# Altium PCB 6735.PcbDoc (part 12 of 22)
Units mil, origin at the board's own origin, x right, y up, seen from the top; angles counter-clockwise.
Board outline 2641.73 x 5165.35 mil, 6 copper layers (Top, Inner Layer 2, Inner Layer 3, Inner Layer 4, Inner Layer 5, Bottom), stack 35.7 mil thick; 1011 components, 790 nets, 4118 pads, 9325 vias.
Unrouted connection lines stored in the file: 4610.
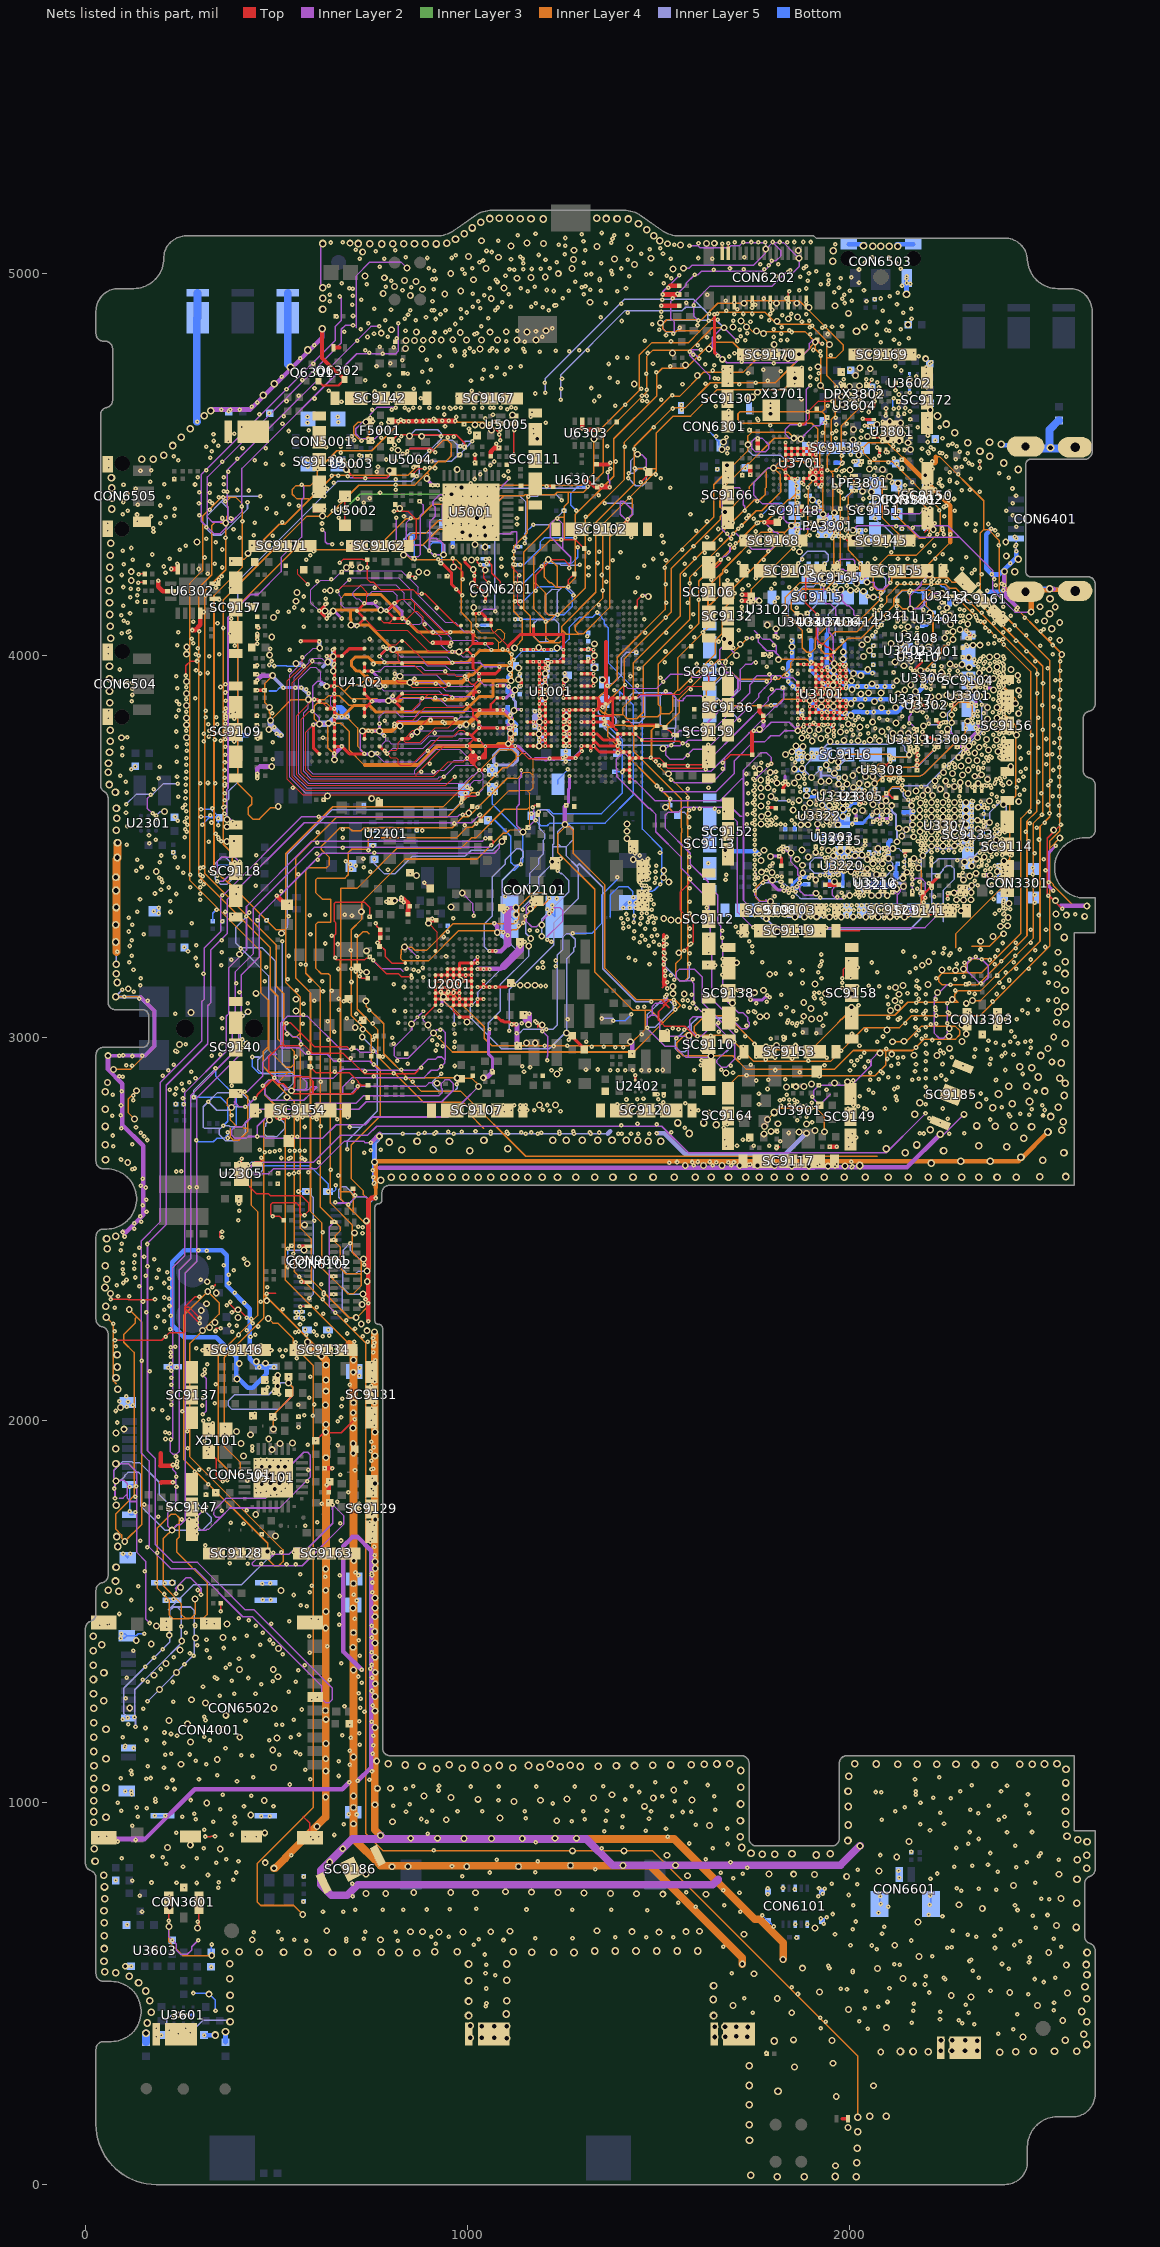
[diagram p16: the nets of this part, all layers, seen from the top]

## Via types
v1: diameter 12, hole 4, Top to Inner Layer 2, 3329 vias
v2: diameter 12, hole 4, Inner Layer 5 to Bottom, 3071 vias
v3: diameter 18, hole 10, Inner Layer 2 to Inner Layer 5, 1928 vias
v4: diameter 10, hole 4, Top to Inner Layer 2, 525 vias
v5: diameter 20, hole 12, Top to Bottom, 472 vias

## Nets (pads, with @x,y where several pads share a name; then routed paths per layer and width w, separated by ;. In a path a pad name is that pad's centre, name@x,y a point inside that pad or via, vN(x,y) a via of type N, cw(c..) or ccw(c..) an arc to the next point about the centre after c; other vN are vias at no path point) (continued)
D_GND: (continued)
  other v2: 198.3,391.09 2047.13,407.53 1923.89,409.43 2285.09,430.29 2235.79,432.18 1922.94,435.97 2165.63,454.93 2038.6,461.57 2303.58,470.19 1049.27,474.48 2098.32,477.69 1864.16,498.54 2466.16,497.6 2207.35,502.34 2042.39,506.13 1048.41,513.45 1976.03,512.76 2506.93,529.83 2250.01,537.41 2337.23,541.21 2198.82,545 1046.68,552.43 2007.31,559.22 2415.44,564.91 1946.64,565.85 119.31,571.09 2130.56,575.33 2468.53,581.97 2313.05,584.82 1044.94,601.79 2069.88,615.15 182.31,618.96 2379.59,618.88 2255.22,619.89 2553.38,621.79 2001.62,626.53 1015.5,626.91 916.76,630.38 682.05,636.44 577.25,637.3 817.16,637.3 2445.78,636.96 227.31,639.09 514.03,641.63 727.95,643.37 2330.12,648.33 2084.1,655.92 440.61,660.01 2269.44,663.5 2394.59,668.24 2015.84,688.15 2478.96,703.32 2206.44,706.05 2074.86,711.2 674.24,713.4 621.41,714.13 1712.74,714.02 1469.55,717.16 705.92,718.49 778.29,718.49 831.51,718.49 893.23,719.55 1153.91,719.51 1273.74,718.72 1375.56,718.72 952.83,720.61 1022.01,721.68 1597.12,726.44 1671.17,731.24 2009.07,730.65 2432.03,730.81 1551.19,737.41 2521.15,746.93 698.97,754.1 1997.06,757.53 1711.17,763.37 1571.76,764.84 1669.11,770.32 2337.23,774.42 2279.84,774.73 2019.37,786.14 238.3,789.58 291.41,789.01 172.77,790.14 349.03,790.71 386.89,796.92 1695.17,801.18 985.56,806.74 2228.41,813.69 1662.26,815.57 1057.75,816.3 1176.64,817.36 2387.38,818.37 2021.09,823.32 1334.27,824.79 1731.53,828.37 959.03,833.28 2320.16,834.15 1687.63,843 2462.37,843.63 1183.01,846.02 2546.75,849.32 1075.79,850.27 1622.49,850.54 368.81,851.16 291.11,853.5 202.12,856 538.3,861.33 2079.31,862.09 2499.34,866.38 2367.57,867.33 911.26,874.68 309.49,879.4 1351.26,879.99 1641,880.02 2278.45,880.6 1680.08,890.99 1579.3,892.36 1177.7,895.91 84.63,897.42 131.51,901.55 595.36,902.57 1523.76,910.19 382.39,914.66 895.33,918.2 2411.18,921.37 2313.53,922.32 2476.59,922.32 1357.63,924.57 1466.17,925.27 310.75,927.87 1518.98,930.94 1678.71,931.44 1404.33,935.19 122.73,939.15 1597.12,941.04 2183.65,942.23 2246.22,944.12 334.47,948.95 1272.31,950.09 2083.16,954.55 1306.14,955.36 878.35,956.42 1474.4,957.5 1152.22,958.54 389.9,962.1 2404.54,962.13 284.84,970.48 2236.74,972.56 2336.28,971.61 1562.84,974.64 2118.23,976.35 93.25,978.1 1364.53,977.65 1647.86,980.12 133.76,986.49 2362.83,991.52 2461.42,992.47 848.63,994.63 183.31,1000.98 1541.59,1002.75 275.23,1006 2264.23,1010.48 2217.78,1012.38 1645.12,1015.78 434.14,1017.61 358.9,1019.88 2172.27,1019.96 2082.21,1026.6 233.03,1034.83 1007.86,1041.34 1081.1,1041.34 1179.82,1041.34 1280.67,1041.34 857.12,1042.4 1354.97,1042.4 1429.28,1042.4 925.06,1043.46 2411.18,1043.67 1627.98,1045.26 2319.22,1044.61 534.59,1046.66 1490.85,1052.11 1571.07,1052.11 396.48,1055.59 227.64,1058.32 296.96,1060.31 588.4,1060.44 2170.37,1060.73 158.91,1061.93 91.85,1063.32 2233.89,1065.47 438.6,1065.75 662.82,1068.95 344.92,1070.42 119.1,1082.88 574.58,1084.89 205.44,1090.15 316.17,1099.18 662.82,1107.22 436.09,1122.15 208.27,1124.6 273.34,1125.21 561.82,1125.29 126.47,1142.05 102.5,1144.17 206.45,1155.17 97.33,1169.79 310.94,1172.07 239.48,1174.52 672.38,1175.26 558.63,1176.32 206.76,1182.71 515.05,1202.9 310.94,1224.16 730,1237.42 565.84,1242.91 441.69,1246.48 677.7,1251.8 351.33,1278.38 389.6,1283.69 444.88,1283.69 532.06,1289.01 307.5,1301.91 162.49,1315.35 550.13,1315.58 639.43,1320.9 344.06,1323.19 196.64,1348.85 745,1349.95 155.95,1354.46 573.52,1359.17 259.03,1361.16 377.67,1361.6 669.58,1363.76 179.43,1378.29 230.75,1379.33 283.55,1383.77 587.34,1391.06 316.98,1397.65 201.81,1400.67 632.13,1408.1 457.69,1412.82 316.68,1425.27 585.82,1434.71 422.24,1435.7 250.58,1460.05 287.64,1460.33 748.75,1462.47 62.58,1466.24 486.5,1467.24 533.59,1474.13 316.98,1475.27 401.55,1482.01 88.2,1492.85 563.33,1515.25 119.73,1529.31 138.45,1565.77 185.31,1574.09 749.69,1593.75 561.73,1596.88 187.75,1652.98 161.19,1667.83 313.26,1672.74 143.42,1684.71 668.59,1685 750.62,1690.33 286.78,1716.26 574.62,1723.43 413.6,1728.84 666.62,1730.33 380.45,1731.54 606.51,1732.3 271.26,1740 190.6,1747 751.56,1757.84 356.77,1763.34 421.53,1763.94 315.78,1771.82 153.47,1779.26 617.92,1780.93 658.74,1786.49 130.65,1799.96 687.48,1811.08 752.5,1815.04 631.45,1830.32 321.59,1831.67 358.8,1839.79 580.37,1840.47 423.75,1841.82 666.63,1856.94 285.64,1865.28 582.4,1869.56 705.19,1868.88 322.12,1871.53 753.44,1872.24 238.73,1886.13 316.91,1919.48 267.92,1926.78 754.38,1929.44 660.37,1934.08 581.72,1935.86 310.65,1944.5 208.5,1968.48 265.83,1970.56 557.37,1981.19 755.31,1986.64 332.54,1991.41 660.37,1996.62 594.92,2010.96 253.32,2022.68 201.2,2025.81 177.23,2028.93 556.69,2040.73 337.76,2044.57 756.25,2043.84 671.84,2056.04 585.44,2058.32 340.88,2093.56 757.19,2101.04 588.15,2113.12 311.7,2122.75 167.85,2127.96 238.31,2138.09 147,2155.06 758.13,2156.36 553.01,2162.36 515.48,2167.57 594.7,2174.87 486.67,2182.8 318.47,2187.38 290.33,2188.42 235.08,2191.55 666.63,2191.55 623.33,2192.28 458.25,2196.33 756.16,2202.39 549.59,2203.78 703.62,2204.79 210.06,2218.65 431.8,2218.66 605.06,2222.04 401.27,2223.98 685.18,2226.69 548.91,2230.16 184.25,2241.66 451.49,2245.05 206.48,2258.7 433.61,2264.67 189.22,2271.81 586.73,2277.37 621.99,2277.93 158.54,2282.26 206.54,2289.3 515.74,2290.09 76.19,2294.2 605.07,2295.28 369.17,2300.5 415.25,2307.45 150.55,2310.28 458.54,2310.03 181.92,2316.63 205.9,2320.82 85.23,2323.68 114.69,2323.93 623.12,2328.71 390.76,2332.92 172.32,2345.11 140.75,2349.99 81.88,2352.82 375.6,2358.18 206.58,2358.71 107.39,2366.67 130.45,2373.25 186.09,2372.92 158.17,2378.26 214.18,2386.98 191.5,2392.91 97.63,2395.02 127.19,2395.85 162.34,2402.36 361.98,2404.83 127.49,2412.39 180.34,2420.99 322.92,2424.45 153.25,2427.13 129.44,2431.86 295.68,2444.35 316.9,2443.67 141.1,2451.35 161.17,2460.75 102.18,2480.42 621.25,2491.06 128.17,2500.19 713.69,2505.94 145.68,2518.83 598.49,2521.32 159.8,2545.38 158.67,2576.45 158.11,2608.65 272.46,2609.17 291.24,2609.59 149.63,2631.24 661.55,2639.98 237.45,2650.37 250.68,2651.61 641.71,2655.01 122.52,2656.66 2006.96,2664.22 1915.23,2665.35 1961.09,2664.78 1591.04,2666.48 1823.49,2666.48 1869.36,2665.91 1641.72,2667.33 1689.57,2666.76 1782.72,2667.05 1736,2667.61 610.44,2674.86 574.36,2680.87 92.58,2682.65 532.26,2683.88 72.66,2716.51 1704.67,2717.7 1748.92,2717.7 1788.59,2718.21 1817.58,2729.4 162.19,2732.81 153.25,2742.3 71.06,2744.56 1445.76,2749.5 2259.51,2749.06 1403.59,2749.69 2182.5,2750.2 2299.15,2750.2 1840.47,2751.27 144.27,2751.64 887.39,2752.22 1192.87,2751.87 1344.43,2752.51 917.1,2752.92 1139.74,2753.27 1166.65,2752.92 1532.99,2753.49 2044.05,2753.31 949.26,2753.97 1101.99,2753.97 1239.35,2753.97 1319.74,2753.62 2078.03,2754.16 984.91,2755.01 1060.4,2755.01 1275.7,2755.36 1020.56,2756.06 1567.56,2765 132.24,2765.93 573.61,2766.99 615.99,2769.08 1402.28,2771.14 1679.65,2774.09 1444.35,2775.08 1495.19,2774.64 1862.34,2784.33 2367.1,2786.44 605.52,2786.87 658.37,2786.87 553.72,2787.92 1710.78,2787.89 2256.03,2788.38 2207.16,2789.73 686.1,2792.63 1735.7,2795.51 70.26,2795.87 2469.03,2798.9 2415.8,2800.03 1631.95,2807.25 1666.02,2807.25 2509.8,2811.35 2243.47,2815.29 2037.68,2816.18 418.21,2820.06 1878.43,2820.49 2021.41,2821.43 1121.65,2823.38 1151.83,2823.49 1093.49,2823.94 1137.31,2823.78 1208.73,2824.42 1502.36,2823.91 1762.15,2826.03 1391.36,2826.6 1568.98,2828.86 1862.43,2832.72 125.12,2837.11 1817.08,2836.92 2122.87,2836.81 255.13,2842.09 1901.53,2846.55 2026.12,2847.77 124.82,2849.29 2275.65,2849.5 71.66,2851.19 2212.54,2851.61 234.31,2853.09 1762.15,2853.49 2317.73,2854.41 2060.99,2856.53 399.18,2859.11 2241.23,2859.67 256.2,2863.62 1938.94,2864.18 220.46,2864.9 1784.48,2866.32 2116.45,2866.34 237.28,2867.55 382.28,2874.99 252.28,2879.64 271.5,2883.55 615.28,2884.84 699.64,2884.84 855.78,2885.15 1755.02,2888.59 2009.28,2888.57 2251.56,2890.32 2382.96,2890.18 1786.62,2890.91 1830.44,2891.44 2180.29,2893.01 838.51,2894.45 2224.69,2893.96 287.94,2894.79 2126.44,2896.79 88.09,2900.09 754.34,2900.13 1919.53,2899.91 1729.6,2901.81 806.68,2907.31 2085.81,2908.13 2053.4,2909.02 276.49,2910.97 1147.35,2911.02 1868.93,2910.68 2268.15,2910.96 652.4,2911.84 731.35,2912.51 1219.32,2915.23 1372.76,2915.4 1392.55,2915.29 1412.34,2915.18 1432.13,2915.08 1453.85,2914.97 1474.72,2915.08 1495.58,2915.18 1593.04,2915.07 826.51,2916.56 1309.52,2916.16 1510.31,2916.04 1804.27,2915.97 1340.15,2917.26 1242.99,2917.9 1163.12,2922.96 931.33,2925.17 1142.89,2925.99 965.85,2926.61 1688.65,2926.73 106.53,2928.55 1933.7,2928.25 1609.82,2928.8 753.95,2930.49 1740.97,2930.14 2366.13,2931.56 843.16,2932.08 2243.51,2931.65 2003.62,2938.64 2047.7,2939.03 815.34,2940.18 1611.86,2941.52 1891.37,2940.61 663.6,2941.75 1779.69,2943.52 1848.67,2945.25 2097.52,2944.88 694.24,2946.93 1710.52,2948.09 1804.1,2948.09 1939.37,2948.09 2139.95,2949.09 2028,2950.3 2266.19,2949.79 1550.9,2950.95 1754.77,2951.14 2325.78,2950.64 2397.34,2952.6 330.16,2953.79 352.91,2956.65 1908.15,2959.59 2200.96,2958.91 2465.71,2959.61 235.59,2965.85 753.45,2965.62 1878.91,2966.04 916.31,2967.15 1977.15,2966.59 2236.53,2967.08 1613.89,2968.47 965.31,2975.09 1407.29,2975.46 1386.44,2975.67 1324.8,2976.7 1355.77,2977.11 1721.13,2977.38 935.31,2978.09 1224.95,2978.77 1260.27,2978.97 2025.17,2979.47 1201.62,2979.8 1857.73,2981.35 2402.95,2980.65 920.31,2982.09 1750.42,2983.99 806.31,2985.09 356.47,2986.5 2439.77,2986.26 1619.99,2987.29 1309.72,2989.5 966.31,2990.09 2362.63,2992.21 2472.73,2991.87 907.01,2994.23 2215.6,2994.46 635.12,2994.7 753.15,2995.23 1792.54,2997.36 2187.64,2997.48 1546.03,2999.14 802.94,3000.09 926.31,3002.09 1825.26,3003.1 2086.65,3003.8 1725.89,3004.66 1636.27,3006.11 1854.91,3008.63 1455.41,3009.95 2005.5,3010.44 966.31,3011.09 1912.15,3012.59 1877.02,3015.17 650.48,3016.43 1657.12,3015.77 2421.88,3017.82 1702.44,3019.1 2043.05,3020.02 2180.39,3020.02 928.31,3021.09 357.57,3025.39 1859.9,3031.36 1729.63,3032.17 1929.65,3032.09 2211.3,3035.79 568.31,3037.09 751.35,3037.69 1141.94,3038.11 2144.86,3038.16 1752.06,3038.95 818.31,3040.09 2347.51,3042.29 634.17,3043.38 1176.31,3044.09 1838.28,3046.35 2125.83,3048.24 1703.79,3049.32 2406.45,3048.68 357.29,3051.68 683.54,3051.66 2100.12,3053.21 2003.15,3057.09 569.31,3061.09 1819.38,3061.46 709.01,3062.5 1936.65,3063.09 2192.57,3063.07 235.26,3063.64 2259.65,3064.02 2465.71,3064.81 1752.51,3067.37 2313.5,3066.85 836.89,3070.06 1852.04,3070.03 807.41,3071.15 926.31,3071.09 2162.34,3070.63 742.92,3072.21 2224.72,3072.29 2491.66,3073.23 662.89,3073.8 1834.19,3080.02 1445.22,3080.65 1461.75,3081.43 2022.65,3085.59 570.56,3089.44 1755.22,3090.38 1932.28,3090.38 424.28,3091.11 1540.07,3092.37 1782.74,3094.44 2374.19,3094.27 598.07,3096.82 2467.01,3099.33 2518.89,3098.94 2180.29,3101.81 662.33,3102.91 1905.06,3107.5 1784.09,3111.13 1820.72,3113.2 2150.76,3117.16 403.08,3119.48 963.31,3119.09 929.09,3120.91 948.95,3120.83 621.4,3121.86 644.15,3123.44 552.4,3124.62 1521.64,3129.22 2181.23,3129.21 833.31,3133.09 2018.59,3134.68 2076.91,3134.79 2049.91,3136.76 806.31,3140.09 394.43,3142.64 2312.82,3143.36 2342.98,3142.66 1876.07,3143.66 2391.37,3144.76 2519.68,3144.88 695.95,3146.35 1522.69,3145.86 619.3,3148.29 469.16,3148.62 586.67,3149.28 2175.56,3149.99 2417.32,3152.48 528.8,3153.63 1925.65,3155.59 853.31,3157.09 2002.15,3157.59 883.31,3159.09 1844.89,3167.28 308.85,3168.24 2071.27,3171.47 2509.78,3171.02 1917.64,3172 871.31,3174.09 1876.07,3176.72 859.31,3178.09 661.62,3180.35 695.95,3180.55 840.31,3181.09 2435.79,3180.73 2468.52,3181.23 2172.73,3182.11 882.31,3184.09 1183.21,3183.79 1197.07,3184.23 2020.62,3184.28 472.83,3184.65 292.75,3189.35 355.77,3189.82 1648.15,3189.75 576.17,3191.41 1923.31,3190.9 562.91,3193.15 1475.78,3192.77 2509.78,3194.38 114.76,3197.44 1770.3,3197.56 2057.47,3197.23 1195.71,3197.82 1842.51,3198.17 1229.95,3202.54 1997.65,3202.09 752.68,3203.49 1438.85,3202.76 2473.43,3205.08 288.33,3209.03 653.38,3210.21 1421.83,3210.06 2169.9,3212.35 532.26,3214.35 943.31,3214.09 2259.71,3215.99 1515.31,3221.09 1489.95,3221.83 1580.8,3221.91 2219.27,3222.85 356.32,3224.16 2139.94,3226.03 693.59,3228.89 2387.19,3229.35 2484.56,3229.7 2287.99,3231.24 2341.84,3231.24 2247.37,3234.08 2510.97,3237.82 115.54,3240.44 1473.31,3241.09 289.93,3241.96 1501.31,3244.09 1581.09,3243.88 1520.31,3245.09 659.95,3245.64 627.6,3247.08 2400.42,3248.25 2472.73,3248.56 764.06,3249 1450.31,3250.09 1486.31,3252.09 356.6,3255.14 1464.96,3257 1434.31,3261.09 937.51,3264.07 1521.31,3264.09 1481.31,3266.09 1580.56,3266.17 708.58,3266.78 1455.31,3267.09 644.59,3267.62 1496.31,3269.09 1718.06,3270.11 152.31,3271.09 588.73,3270.72 1731.93,3275.26 1707.94,3276.96 113.6,3278.4 1435.31,3279.09 1760.68,3279.07 1162.07,3281.46 1181.99,3280.91 2473.43,3282.93 2513.08,3283.23 1489.31,3284.09 1464.31,3286.09 1580.56,3286.16 1406.78,3287 1701.31,3290.56 1747.58,3290.06 1421.31,3291.09 1134.11,3292.9 1719.9,3292.88 1451.31,3298.09 277.89,3300.19 1407.31,3300.09 1145.42,3301.49 1487.31,3301.09 1625.31,3301.09 1471.31,3303.09 1419.31,3310.09 1402.31,3313.09 2089.65,3313.59 113.21,3314.03 1455.95,3314.49 1962.65,3314.59 2057.65,3314.59 2122.52,3315.04 1897.75,3316.27 1931.65,3316.59 1993.65,3316.59 2025.65,3316.59 1151.37,3317.97 1482.61,3317.97 697.31,3320.09 586.52,3320.69 2494.47,3321.5 627.84,3322.03 677.95,3321.84 2401.65,3323.59 1415.31,3324.09 2379.65,3324.59 1455.95,3326.49 1468.95,3326.49 1581.31,3326.09 2240.33,3327.26 222.47,3329.5 365.95,3329.49 2274.65,3329.59 1720.29,3333.06 2390.65,3333.59 2207.36,3333.92 1481.31,3335.09 2252.72,3335.3 2401.65,3339.59 2273.65,3342.59 2306.65,3343.59 1803.65,3346.59 2218.65,3348.59 1486.95,3349.83 532.95,3352.49 1470.31,3352.09 2483.58,3353.7 832.26,3355.13 2401.65,3354.59 1581.31,3356.09 222.19,3357.06 787.33,3356.63 1480.77,3361.91 2376.65,3362.59 1233.24,3364.7 826.31,3367.29 1467.39,3367.09 1922.06,3367.3 1433.31,3368.09 1966.65,3368.59 1984.65,3368.59 2024.65,3368.59 2220.65,3369.59 1803.16,3370.61 2519.13,3371.86 357.43,3372.81 2036.65,3372.59 2014.65,3375.59 2291.65,3375.59 2483.22,3375.05 393.95,3376.49 237.95,3376.6 181.85,3377.87 1978.65,3379.59 2411.94,3378.77 2369.65,3380.59 2162.65,3384.59 197.61,3387.32 2017.65,3387.59 2037.65,3387.59 1581.17,3391.03 2176.65,3390.59 2301.65,3391.59 2419.33,3393.34 217.78,3393.63 273.89,3394.26 400.3,3394.52 1861.65,3395.59 2285.65,3394.59 2480.43,3397.32 445.96,3398.42 1466.95,3398.49 2022.65,3398.59 309.95,3401.49 2163.65,3401.59 2370.8,3402.42 2402.65,3404.59 1868.21,3406.21 2520.75,3407.23 2182.25,3408.33 2326.65,3411.59 2479.4,3411.21 1455.62,3412.82 1467.95,3413.49 198.24,3415.06 2162.65,3414.59 1581.24,3416.57 1869.61,3418.2 1892.35,3418.33 162.3,3418.84 400.02,3419.34 1760.65,3418.59 2401.65,3418.59 1822.2,3421.44 1946.65,3420.59 306.95,3423.49 1810.28,3423.17 1922.65,3425.59 1935.65,3425.59 1968.62,3425.42 274.52,3427.04 1956.66,3427.22 2163.65,3427.59 2478.88,3428.24 256.19,3431.75 2295.65,3432.59 745.59,3434.81 133.3,3437.12 1949.76,3437.06 2402.65,3436.59 1936.79,3438.02 1962.67,3437.99 1782.71,3439.17 2511.9,3438.7 791.57,3440.1 695.71,3441.4 2163.65,3440.59 2368.65,3443.59 2296.65,3445.59 241.74,3445.95 307.95,3446.49 1580.14,3446.03 2478.88,3445.61 146.54,3447.21 728.44,3446.72 2337.65,3447.59 2398.49,3448.23 1790.47,3448.61 447.14,3451.26 2413.72,3452.18 2165.65,3453.59 1798.7,3457.37 680.59,3462.48 2182.65,3462.59 2280.65,3464.59 2315.65,3465.59 135.66,3466.4 608.19,3466.08 727.39,3468.42 2507.77,3467.93 1934.65,3471.59 233.54,3472.43 1972.65,3473.59 1985.65,3473.59 1998.65,3473.59 257.5,3473.69 1579.63,3474.1 446.96,3478.18 2418.5,3479.11 1926.65,3481.59 2075.01,3480.61 2088.65,3480.59 605.77,3482.1 2483.75,3483.18 755.62,3484.33 1503.22,3484.14 2339.65,3484.59 740.49,3490.71 2009.65,3491.59 2022.65,3491.59 1959.65,3493.59 1819.06,3495.5 1926.65,3494.59 2352.65,3495.59 2422.56,3495 2096.65,3497.59 2192.65,3497.59 673.52,3497.86 1579.63,3497.7 2293.65,3499.59 2384.65,3498.59 2228.65,3503.59 2258.65,3503.59 107.79,3505.41 2188.65,3509.59 606.68,3510.83 2317.65,3511.59 322.73,3513.48 2177.71,3514.56 2467.94,3514.26 2198.65,3516.59 2228.65,3516.59 2258.65,3516.59 2288.65,3516.59 2401.65,3519.59 2494.89,3519.07 348.28,3519.9 1579.31,3522.09 672.93,3523.36 2187.65,3522.59 2324.65,3524.59 2198.65,3529.59 2228.65,3529.59 2258.65,3529.59 2288.65,3529.59 340.61,3534.25 2391.65,3534.59 607.29,3537.74 2405.31,3538.09 2460.58,3539.6 2165.65,3541.59 866.95,3542.83 881.58,3542.68 2198.65,3542.59 2228.65,3542.59 2258.65,3542.59 2288.65,3542.59 2318.65,3542.59 738.91,3544.09 260.65,3545.56 672.93,3545.46 2489.28,3549.94 1579.31,3551.09 108.96,3553.35 1930.65,3555.59 1947.65,3554.59 2198.65,3555.59 2228.65,3555.59 2258.65,3555.59 2288.65,3555.59 2318.65,3555.59 2350.65,3554.59 992.74,3556.64 1782.65,3557.59 1794.65,3557.59 1806.65,3557.59 1729.65,3558.59 1818.65,3559.59 2405.31,3559.09 965.36,3561.08 1022.85,3560.84 1744.65,3561.59 2470.41,3561.68 329.78,3563.52 2509.64,3562.76 1954.65,3565.59 260.02,3565.73 1847.65,3569.59 2198.65,3568.59 2228.65,3568.59 2258.65,3568.59 2288.65,3568.59 2318.65,3568.59 2348.65,3568.59 1782.65,3570.59 1794.65,3570.59 1923.65,3573.59 1964.68,3572.69 1806.65,3575.59 1910.65,3575.59 1952.65,3577.59 610.31,3579.09 1862.65,3578.59 2198.65,3581.59 2228.65,3581.59 2258.65,3581.59 2288.65,3581.59 2318.65,3581.59 1030.9,3582.54 2106.88,3582.51 326.57,3582.77 1932.65,3582.59 1996.65,3583.59 2058.85,3583.31 2502.58,3583.4 2085.03,3583.84 1731.65,3585.59 1966.65,3584.59 1745.65,3587.59 1944.65,3586.59 2350.65,3586.59 2522.25,3588.24 106.03,3589.6 2471.03,3591.34 1954.65,3593.59 1936.65,3595.59 2198.65,3594.59 2228.65,3594.59 2258.65,3594.59 2288.65,3594.59 2318.65,3594.59 1579.31,3595.98 1966.65,3597.59 1996.65,3596.59 332.19,3601.22 2360.65,3600.59 254.03,3602.29 360.26,3602.82 1025.3,3603.2 1784.88,3602.64 2376.94,3606.36 2198.65,3607.59 2228.65,3607.59 2258.65,3607.59 2288.65,3607.59 2318.65,3607.59 1911.65,3609.59 1993.65,3608.59 2351.65,3609.59 2518.34,3609.47 1966.65,3610.59 1731.65,3612.59 1850.65,3613.59 2040.65,3613.59 1745.65,3615.59 1786.65,3615.59 2003.65,3617.59 2386.94,3617.36 2493.17,3617.32 2322.68,3619.59 2198.65,3620.59 2228.65,3620.59 2258.65,3620.59 2288.65,3620.59 1914.65,3622.59 1940.65,3622.59 1953.65,3622.59 1966.65,3623.59 2152.65,3623.59 2165.65,3622.59 1927.65,3624.59 1994.65,3625.59 1575.31,3628.09 2176.65,3628.59 242.68,3630.66 2530.67,3632.04 2063.65,3637.59 1733.65,3639.59 2500.5,3639.76 107.79,3641.64 1870.34,3643.99 1746.65,3646.59 1801.65,3647.59 2455.81,3649.12 1575.31,3652.09 1630.11,3653.97 2320.78,3655.44 1868.65,3657.59 2186.65,3656.59 2221.65,3656.59 2258.65,3659.59 2353.06,3661.5 2366.65,3660.59 2518.65,3661.59 1838.72,3662.91 1074.31,3664.09 364.98,3664.7 1730.65,3665.59 1881.65,3664.59 2396.77,3665.05 1824.65,3665.7 300.05,3666.6 320.56,3666.99 339.13,3666.6 2380.65,3668.59 105.45,3669.7 1795.65,3673.59 2526.05,3672.96 2271.65,3674.59 1746.65,3677.59 1880.65,3677.59 2392.65,3679.59 1785.65,3680.59 1806.65,3681.59 2233.65,3682.59 2454.15,3683.59 90.96,3686.13 1728.65,3690.59 2493.17,3695.72 1806.65,3696.59 2052.88,3700.14 2532.28,3700.86 1622.6,3702.89 2459.99,3704.67 2348.7,3706.57 1748.65,3707.59 2258.65,3706.59 2275.06,3707 2335.65,3707.59 2046.65,3711.59 2059.65,3711.59 2322.65,3710.59 1576.31,3712.09 1784.65,3713.59 2514.17,3715.57 1627.42,3717.11 1767.65,3719.59 2269.65,3719.59 2350.65,3719.59 1856.65,3721.59 1875.65,3721.59 1256.31,3723.09 2408.07,3729.82 1847.65,3730.59 2393.65,3731.59 2356.65,3733.59 2370.65,3733.59 1860.65,3734.59 1873.65,3734.59 1905.65,3734.59 96.41,3739.1 1575.31,3739.09 1969.65,3738.59 2344.65,3740.59 2515.65,3740.59 2529.84,3742.5 2310.65,3743.59 1913.65,3744.59 2403.06,3745 2467.53,3746.56 1865.65,3746.59 1878.65,3746.59 1900.65,3746.59 2297.65,3747.59 1629.42,3748.25 1256.31,3750.09 782.79,3751.07 895.01,3751.7 2168.65,3752.59 1926.47,3756.66 96.11,3759.37 2493.17,3758.94 2158.65,3761.59 2376.65,3763.59 2396.61,3763.09 2409.06,3764 1575.31,3766.09 2353.56,3766 1629.02,3767.41 2188.55,3769.11 2324.65,3771.59 2534.89,3771.72 1966.65,3773.59 2037.65,3773.59 389.4,3775.52 2003.65,3775.59 2139.65,3774.59 2155.65,3775.59 309.09,3776.01 354.22,3777.99 338.87,3779.63 2120.65,3781.59 2514.04,3782.14 1644.15,3783.59 2401.65,3782.59 621.47,3785.41 322.72,3788.27 1889.65,3788.59 1939.65,3789.59 2066.65,3789.59 2248.65,3789.59 1575.31,3790.09 2095.65,3790.59 2475.91,3791.79 367.07,3793.42 1908.65,3793.59 2008.65,3793.59 2374.65,3793.59 1253.95,3795.49 1957.65,3794.59 2026.65,3794.59 309.91,3796.09 2047.65,3796.59 2349.65,3796.59 350.36,3797.92 913.4,3797.79 1878.65,3799.59 2240.24,3800.17 1991.65,3800.59 2190.65,3800.59 324.01,3803.7 391.7,3805.47 2401.65,3804.59 2339.31,3806.09 1573.22,3807.03 2003.65,3806.59 2504.83,3806.68 2167.65,3808.59 2303.65,3809.59 367.51,3809.91 2066.65,3810.59 2100.65,3810.59 1661.86,3812.21 2413.56,3812.5 1878.65,3813.59 380.57,3815.27 1979.65,3815.59 2045.65,3815.59 2141.65,3814.59 1931.65,3817.59 2010.65,3817.59 1014.19,3818.1 1956.06,3818.18 2533.63,3818.37 321.44,3820.41 344.58,3821.05 2374.65,3821.59 940.03,3822.91 2155.65,3823.59 2349.65,3822.59 1905.65,3824.59 2244.65,3825.59 1253.95,3827.49 2401.65,3826.59 783.1,3830.04 2013.65,3831.59 2033.65,3833.59 2097.65,3832.59 2415.06,3833.5 366.43,3834.55 389.49,3834.72 2076.65,3836.59 2493.17,3837.34 341.95,3838.49 314.45,3839.13 2200.65,3839.59 2022.65,3840.59 2136.65,3841.59 1874.65,3844.59 2402.65,3846.59 379.93,3848.05 2350.65,3849.59 2373.65,3851.59 364.3,3852.75 391.47,3852.66 1939.84,3852.92 2190.65,3852.59 1175.95,3854.49 1188.42,3854.73 314.19,3856.22 244.03,3856.89 1875.65,3857.59 2417.06,3857 2275.65,3859.59 2400.65,3862.59 1709.38,3863.6 2533.41,3866.07 2503.61,3870.48 2264.65,3870.59 2344.93,3871.83 245.06,3873.34 2213.65,3876.59 121.61,3881.07 2388.65,3881.59 2402.65,3881.59 703.45,3881.95 2293.65,3883.59 940.65,3885.96 2374.65,3886.59 286.95,3888.49 2412.06,3893.5 2532.37,3892.97 122.24,3897.27 2389.65,3896.59 2277.65,3900.59 2490.64,3901.82 366.31,3904.09 2400.65,3909.59 1583.6,3912.55 122.87,3913.47 1795.65,3912.59 1939.68,3912.89 2211.65,3912.59 1824.97,3915.68 2353.65,3916.59 353.29,3918.14 2113.84,3919.42 1443.47,3921.65 2387.65,3923.59 2338.65,3925.59 2401.65,3924.59 1929.84,3926.42 916.08,3926.95 2364.65,3927.59 2505.37,3927.53 110.03,3929.05 122.87,3929.03 2211.65,3928.59 89.42,3930.72 748.39,3932.85 1582.93,3934.68 1973.34,3936.42 2406.06,3936.5 2537.93,3936.23 2335.65,3938.59 2264.18,3940.39 2393.06,3940 1804.65,3941.59 1504.45,3942.37 2189.84,3943.42 2294.65,3944.59 2322.51,3945.11 992.96,3946.32 1426.05,3946.17 1835.47,3950.26 1789.65,3951.59 2309.65,3951.59 1135.95,3952.49 1863.34,3952.42 2490.76,3952.08 299.95,3953.49 2059.15,3953.59 2386.56,3954 319.54,3954.78 2400.65,3954.59 2114.84,3956.42 1586.18,3957.07 1609.31,3958.09 941.33,3959.25 2282.56,3960 1848.31,3960.65 289.31,3962.09 2260.68,3961.89 2203.18,3963.39 89.85,3963.95 2349.65,3965.59 1447.42,3965.96 1824.65,3967.59 2403.06,3967.5 2517.19,3967.58 2336.06,3970.5 1782.65,3970.59 1620.87,3971.7 494.39,3973.09 2218.93,3973.38 2239.68,3972.89 2277.68,3973.89 480.81,3975.65 2061.64,3976.05 753.55,3978.31 1598.92,3978.21 2350.65,3979.59 1109.95,3981.49 1673.77,3980.88 1690.76,3980.76 2328.65,3980.59 2399.65,3980.59 1657.95,3981.7 781.81,3982.76 1515.54,3983.11 1898.84,3983.42 2485.5,3985.39 2341.65,3991.59 324.35,3998.16 1788.65,3998.59 2401.65,3998.59 296.01,4000.02 1895.34,4001.42 2062.4,4001.41 2530.5,4003.51 349.72,4003.6 1848.2,4007.29 1517.64,4011.09 2462.12,4011.11 1091.8,4017.11 482.95,4018.49 779.36,4023.02 390.68,4025.55 953.77,4024.94 2061.77,4025.75 2498.23,4025.74 239.62,4027.52 1800.65,4027.59 2304.65,4028.59 2257.18,4030.89 281.81,4032.13 1656.31,4037.09 1847.26,4039.15 1980.43,4039.43 2434.65,4039.16 2400.65,4042.59 743.76,4043.71 278.37,4044.74 2306.65,4045.59 2216.46,4045.87 1811.65,4046.59 1592.84,4048.55 2058.86,4052.8 2324.65,4052.59 2461.56,4053.56 378.89,4057.01 95.36,4058.61 2311.65,4058.59 1464.5,4059.63 1519.04,4060.06 110.8,4061.22 242.86,4061.22 1615.61,4061.57 2254.65,4061.59 2401.65,4061.59 297.46,4064.28 2499.53,4064.29 2417.7,4068.38 360.63,4072.53 1583.15,4075.59 2082.54,4080.2 2431.21,4080.11 2401.65,4081.59 345.49,4084.72 2005.47,4085.4 2376.25,4084.75 2037.63,4085.78 843.96,4086.93 281.66,4089.13 1853.55,4089.3 1886.69,4088.76 1900.97,4088.65 1952.97,4088.69 1986,4089.06 2352.65,4088.59 99.91,4091.17 2296.12,4091.2 2334.65,4091.59 1639.2,4091.67 2247.21,4093.73 1462.45,4094.87 381.63,4097.18 2378.65,4096.59 2401.65,4097.59 2220.42,4098.26 2457.45,4099.36 1518.69,4099.93 2295.62,4105.04 2328.65,4105.59 2421.06,4105 1590.65,4108.09 2366.65,4108.59 116.62,4110.55 2400.65,4111.59 1648.97,4112 2344.65,4112.59 308.89,4114.32 2320.65,4117.59 787.54,4117.84 2298.95,4119.04 2192.18,4119.89 2435.82,4120.4 333.24,4123.66 919.54,4124.84 2378.65,4124.59 2401.65,4127.59 375.94,4127.93 2364.56,4130 98.55,4130.65 1343.47,4132.81 2336.62,4133.36 627.08,4134.63 1519.39,4138.4 1575.65,4138.09 2315.65,4138.59 1733.65,4140.59 1746.65,4140.59 1803.65,4140.59 759.08,4141.63 349.58,4146.03 1605.04,4146.17 628.95,4148.49 2294.97,4147.87 2397.65,4151.59 1810.87,4152.11 116.82,4152.87 2341.06,4153 2378.65,4152.59 314.84,4158.29 1589.53,4159.31 2325.36,4159.79 1699.28,4163.43 2296.65,4163.59 1437.99,4165.95 625.42,4170.36 1353.26,4170.58 2016.65,4169.86 2401.65,4171.59 119.03,4175.53 1794.57,4174.64 2056.56,4175.5 341.46,4177.52 757.42,4177.36 380.03,4177.62 1841.65,4178.59 98.55,4179.67 1734.77,4183.82 1962.97,4184.91 2381.65,4184.59 2294.97,4186.44 2335.88,4186.44 1518.69,4186.67 1803.95,4187.99 1581.45,4189.28 2397.65,4188.59 1124.25,4190.08 1947.64,4192.85 1363.05,4193.66 1980.35,4195.02 1679.88,4197.41 1704.77,4197.73 642.95,4199.49 1636.76,4199.04 1992.14,4200.81 2218.31,4200.65 2377.65,4200.59 1444.89,4203.46 1753.95,4202.99 2011.16,4206.6 1316.18,4210.45 94.76,4211.23 1350.46,4211.15 2064.81,4210.65 1567.61,4211.73 1595.02,4212.82 2344.65,4212.59 2370.65,4212.59 319.94,4214.49 2318.65,4215.59 1978.93,4216.64 1944.52,4218.74 1961.76,4218.97 1676.57,4220.76 2253.31,4220.65 1732.9,4223 2327.09,4225.34 296.72,4226.82 2018.06,4228.5 2294.39,4227.94 1365.85,4230.04 1515.19,4230.04 357.75,4230.84 1316.18,4231.44 2185.81,4233.15 164.4,4236.24 1461.68,4235.63 2238.31,4235.65 99.91,4239.57 338.72,4240.51 1567.85,4241.06 2046.31,4242.09 1339.97,4242.63 1638.92,4243 1708.89,4243 382.75,4247.74 2170.81,4248.15 1379.41,4250.07 1518.89,4250.22 123.21,4250.61 1774.24,4251.1 2264.49,4252.12 1485.56,4253.08 1682.32,4253.54 1875.65,4252.59 2125.81,4253.15 2150.81,4253.15 2223.31,4253.15 2065.72,4253.86 1593.65,4255.17 312.24,4256.95 2304.66,4258.11 1654.56,4264.41 174.79,4264.76 2242.8,4265.22 1508.2,4267.11 1620.49,4269 1316.88,4269.91 1399.94,4270.6 1736,4271.44 2108.31,4270.65 2208.31,4270.65 1344.16,4272.01 1786.45,4272.99 97.1,4274.08 357.75,4277.84 1561.82,4277.71 1852.43,4280.23 120.33,4281.77 1696.96,4282.83 1590.9,4286.9 1870.58,4288.42 2095.81,4288.15 2188.31,4288.15 2220.53,4288.33 435.74,4289.16 2389.95,4289.49 2145.18,4290.39 2165.81,4290.15 465.28,4293.06 1512.31,4296.4 340.97,4297.21 1850.54,4296.95 1662.24,4303.36 1319.68,4304.88 316.42,4306.14 2132.65,4307.59 366.41,4308.37 403.73,4308.5 1716.48,4308.04 1427.98,4309.66 1626.19,4309.67 1852.22,4310.22 490.36,4314.24 1507.28,4314.31 1916.16,4314.53 1937.1,4314.23 1958.04,4313.93 1978.98,4313.62 439.93,4315.13 1895.37,4314.84 1995.14,4315.2 1679.58,4318.87 1860.61,4323.57 1753.36,4325.04 1947.3,4325.45 1598.43,4326.57 1967.11,4325.99 1926.14,4326.93 2243.31,4328.09 1790.91,4328.8 1990.16,4330.1 387.39,4330.69 1655.79,4331.47 2136.36,4331.98 177.51,4333.51 1956.86,4336.39 1978.56,4336.39 1937.89,4336.89 2121.68,4338.39 1717.29,4340.58 1863.02,4342.46 1318.28,4343.91 1897.3,4345.66 1967.65,4346.34 2222.25,4346.01 1756.34,4347.09 443.06,4348.19 1693.7,4347.9 515.01,4349 1990.96,4348.63 1626.19,4351.16 410.77,4351.73 1937.89,4357.33 1958.48,4357.02 1978.56,4358.09 382.97,4358.79 662.3,4360.5 1729.5,4360.1 358.26,4361.01 1309.28,4364 2119.23,4364.27 172.07,4364.82 2206.14,4364.97 2246.58,4365.21 1582.89,4369.71 498.77,4372.87 1861.44,4375.5 2127.32,4377.74 110.11,4379.43 647.25,4378.89 2199.26,4378.92 2274.87,4379.35 715,4380.42 474.24,4385.14 2246.16,4389.16 409.14,4390.41 558.16,4392.65 136.67,4394.77 2118.65,4395.59 533.13,4396.04 2072.65,4396.51 331.94,4398.89 728.33,4400.5 1861.87,4400.69 99.14,4401.99 2133.18,4401.99 2185.58,4401.99 365.62,4404.31 665.64,4405.08 1615.3,4405.75 2258.31,4407.09 711.9,4410.1 2272.31,4410.09 744.01,4411.62 2065.45,4411.77 686.26,4412.89 1422.74,4413.29 2162.6,4414.45 2200.92,4414.03 348.31,4415.1 1863.42,4415.04 517.99,4417.67 1342.52,4419.41 596.94,4424.16 770.72,4426.66 2339.98,4428.48 371.01,4428.9 1864.31,4429.09 2191.31,4430.09 2260.02,4429.91 427.66,4432.17 1971.31,4432.09 2292.59,4432.5 396.79,4433.44 2314.22,4434.11 2223.31,4435.09 131.23,4436.98 633.1,4436.77 1529.98,4438.97 1889.31,4440.09 2064.31,4442.09 1860.31,4445.09 1350.84,4446.42 98.51,4447.12 286.67,4447.99 1974.31,4449.09 1007.94,4451.27 2211.31,4451.09 2232.31,4451.09 649.53,4452.23 1874.31,4452.09 2280.31,4452.09 169.35,4454.68 1856.31,4459.09 2261.46,4460.83 1018.77,4462.27 2316.32,4463.1 731.64,4464.2 1504.82,4464.26 293.63,4466.67 867.15,4469.52 1971.31,4469.09 2064.31,4471.09 1492.14,4474.13 2283.28,4474.31 1032.82,4474.79 1366.07,4479.67 2261.46,4480.08 762.61,4481.04 143.95,4484.41 172.47,4484.72 316.06,4485.45 1941.31,4485.09 1964.31,4485.09 1985.31,4485.09 1046.11,4486.99 1653.35,4488.09 1900.31,4489.09 2216.64,4488.84 2066.31,4492.09 2278.41,4492.84 2292.31,4494.09 765.36,4494.82 1059.12,4498.55 705.3,4498.76 2319.92,4499.16 516.9,4499.87 471.48,4502.03 2122.63,4501.73 357.91,4507.44 1069.31,4508.09 1387.55,4508.07 2215.31,4508.09 811.76,4510.78 443.36,4511.77 1903.31,4512.09 2187.21,4511.94 786.57,4513.25 2277.18,4514.1 2301.57,4514.42 396.85,4515.01 2064.31,4515.09 2114.31,4517.09 2252.31,4521.09 721.31,4522.09 2205.85,4529.5 512.58,4530.15 2235.28,4531.2 2099.58,4532.2 2287.31,4533.09 2219.26,4540.44 1908.95,4541.35 1931.31,4542.1 1945.62,4542.14 1960.82,4542.1 1983.79,4541.88 1997.47,4542.47 2011.5,4542.1 2188.75,4541.83 410.91,4543.13 471.48,4543.13 2031.85,4543.03 629.68,4545.55 2071.18,4544.71 1411.1,4546.16 1364.95,4547.49 2279.43,4547.48 2113.31,4548.09 2257.31,4550.09 1892.3,4553.94 2081.31,4572.09 1954.31,4582.09 1987.31,4582.09 1929.31,4583.09 1005.18,4585.14 766.31,4587.09 531.94,4587.85 584.24,4589.77 2121.31,4596.09 1486.53,4598.2 2148.31,4598.09 2177.31,4598.09 2206.31,4598.09 2235.31,4598.09 940.78,4600.45 515.52,4606.82 1992.31,4607.09 1203.87,4609.33 792.64,4611.54 1069.41,4611.85 1760.49,4616.06 825.11,4617.16 911.77,4619.61 1045.72,4621.76 969.79,4624.54 1164.85,4625.16 519.19,4626.77 1066.24,4630.56 938.75,4631.14 455.26,4631.6 1889.31,4638.09 375.33,4639.09 750.13,4643.14 846.17,4642.9 801.2,4643.79 955.66,4646.3 1536.21,4646.69 1068.03,4649.11 1114.38,4650.24 1649.26,4652.44 1385.83,4653.46 2005.3,4654.09 1412.45,4656.33 1669.8,4656.11 669.83,4664.07 1000.55,4664.96 525.97,4666.28 1331.4,4666.35 801.2,4667.59 1506.16,4669.22 1873.31,4671.09 599.29,4672.88 1085.2,4672.7 877.03,4673.76 2065.31,4676.09 702.45,4677.29 972.57,4678.95 1344.36,4679.16 557.85,4679.94 1535.47,4681.53 1030.55,4685.84 1176.37,4685.97 1804.25,4685.92 757.11,4691.4 636.32,4693.16 1010.84,4692.96 1468.01,4695.33 1829.31,4695.32 525.97,4696.61 858.51,4698.45 599.29,4699.33 1244.67,4698.8 1323.83,4700.3 1501.78,4703.15 821.48,4704.62 783.27,4706.48 1562.04,4710.43 1711.02,4709.77 1622.29,4711.09 1681.89,4712.42 1202.02,4713.63 1754.06,4714.4 1392.27,4714.97 896.42,4716.09 732.43,4720.49 1008.65,4719.78 1785.18,4719.7 567.55,4721.38 1037.87,4725.01 1246.83,4724.62 1655.4,4725 1372.24,4727.25 1062.29,4731.27 794.15,4734.6 639.85,4736.36 1097.33,4736.08 843.52,4737.25 1467.15,4737.77 1688.51,4738.9 1733.54,4738.9 605.46,4740.77 1493.18,4741.55 881.43,4743.42 1819.61,4744.2 684.82,4746.06 1640.83,4746.19 903.48,4747.83 1042.59,4748.24 1773.26,4748.17 1076.25,4753.54 1874.42,4752.96 1112.02,4754.18 761.52,4757.53 1139.18,4756.88 1530.37,4757.15 958.14,4758.41 1621.63,4762.08 1369.49,4763.28 596.13,4764.24 1484.86,4763.9 2209.3,4764.09 797.67,4765.46 1800.41,4765.39 1716.98,4769.36 828.53,4773.4 892.9,4774.28 1417.8,4779.43 1391.62,4780.24 926.4,4783.09 991.65,4785.74 1590.51,4787.24 778.32,4790.35 1471.33,4791.87 743.01,4792.79 2052.92,4792.97 2104.19,4795.88 965.06,4801.41 1104.12,4801 1145.64,4802.61 1005.77,4804.23 1064.62,4804.23 806.77,4807.11 769.75,4808.67 1601.77,4812.4 2129.61,4815.89 2080.84,4819.64 1149.26,4821.16 1100.49,4822.37 710.64,4823.52 1463.37,4824.09 1705.73,4825.64 814.96,4830.1 1626.27,4833.59 1657.64,4833.78 1195.57,4834.97 1941.76,4841.6 1024.31,4844.13 913.16,4845.69 677.17,4847.12 941.99,4846.86 1847.42,4846.83 1178.69,4849.37 1129.92,4849.77 2095.43,4852.16 1500.82,4852.9 720.08,4853.63 1221.61,4857 1927.18,4858 1901.97,4862.86 1601.36,4864.38 1483.12,4866.69 1874.62,4873.19 1768.63,4886.56 657.28,4887.08 1652.79,4894.46 1846.76,4894.51 1676.59,4902.45 941.95,4903.47 850.17,4904.14 906.18,4904.14 1796.44,4904.44 799.37,4904.79 981.97,4906.55 1705.73,4906.43 755.73,4908.05 1032.55,4908.75 1079.18,4910.94 1195.99,4911.43 1113.04,4913.14 1165.98,4913.32 1227.25,4916.16 1591.41,4916.7 1752.08,4917.68 1572.32,4923.16 1986.31,4922.72 1675.27,4928.94 721.21,4931.49 2065.31,4932.09 1980.51,4933.89 1774.17,4934.65 1833.69,4934.65 1627.36,4944.22 1013.25,4947.09 1959.25,4951.43 1157.63,4953.44 1225,4954.17 1320.21,4957.84 689.95,4961.45 1298.32,4964.32 1923.95,4972.29 670.92,4975 1345.11,4982 1945.21,4982.38 1073.2,4984.12 916.69,4985.66 1869.98,4992.01 1422.74,4992.65 1806.95,4993.23 1310.69,4997.38 1777.59,4998.24 1479.68,4999.27 1838.8,5004.75 1912.34,5006.1 1375.88,5007.58 1109.35,5010.57 1643.69,5009.65 986.26,5011.3 1722.36,5010.75 898.38,5013.49 1879.81,5013.22 1686.25,5013.81 769.49,5017.89 1765.79,5023.77 1812.11,5023.77 1145.5,5027.33 1030.93,5028.87 1795.43,5033.55 1203.7,5036.14 1418.4,5036.08 781.2,5038.39 1531.3,5038.25 717.72,5038.61 1639.86,5038.97 1602.95,5040.42 894.72,5040.59 958.43,5040.59 838.33,5042.05 1723.22,5042.18 1137.85,5044.25 1453.86,5051.27 1511.04,5051.27 1049.24,5058.9 1476.3,5063.58 1238.08,5074.94 1379,5090.62 1298.03,5103.08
